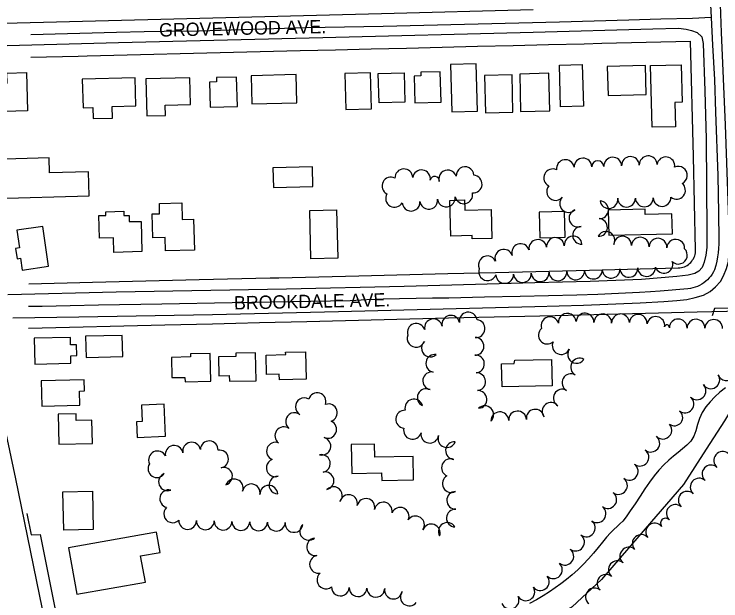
# Model space of a CAD drawing. Extents: x -25029 to 2274964, y -81170 to 687028.
# Drawn here: x -18399 to -17603, y -67227 to -66567 of the extents above; entities that cross this region are included whole.
import ezdxf

# ---------------------------------------------------------------- set-up
doc = ezdxf.new("R2010")
doc.units = 0
for name, color, linetype in [('81911BEA - RW_X_Fee_RW', 7, 'Continuous'), ('BLDG', 7, 'Continuous'), ('CULVERT', 7, 'Continuous'), ('GE_X_CL_2000', 7, 'Continuous'), ('ROAD', 7, 'Continuous'), ('ROAD-NAME', 7, 'Continuous'), ('TREES', 7, 'Continuous'), ('WATER', 7, 'Continuous')]:
    doc.layers.add(name, color=color, linetype=linetype)

msp = doc.modelspace()

# ---------------------------------------------------------------- linework, layer by layer
at = {"layer": '81911BEA - RW_X_Fee_RW'}
for p, q in [((-18379.53, -67152.95), (-18369.44, -67152.7)), ((-18369.44, -67152.7), (-18310.53, -67445.07))]:
    msp.add_line(p, q, dxfattribs=at)
for points in [[(-18380.26, -66615.06), (-18326.66, -66613.75), (-18316.66, -66613.51), (-18256.68, -66612.04), (-18196.7, -66610.58), (-18136.71, -66609.12), (-18076.73, -66607.66), (-18036.74, -66606.68), (-17996.75, -66605.71), (-17956.76, -66604.73), (-17916.77, -66603.75), (-17876.78, -66602.78), (-17836.79, -66601.8), (-17796.81, -66600.83), (-17756.82, -66599.85), (-17736.82, -66599.37), (-17686.84, -66598.15), (-17636.85, -66596.93)], [(-17631.12, -66831.87), (-17633.68, -66726.89), (-17636.85, -66596.93)], [(-17650.63, -66852.35), (-17648.89, -66852.23), (-17647.16, -66851.96), (-17645.47, -66851.54), (-17643.82, -66850.98), (-17642.22, -66850.27), (-17640.7, -66849.43), (-17639.25, -66848.45), (-17637.89, -66847.36), (-17636.63, -66846.15), (-17635.48, -66844.83), (-17634.46, -66843.42), (-17633.56, -66841.93), (-17632.79, -66840.36), (-17632.16, -66838.74), (-17631.68, -66837.06), (-17631.34, -66835.35), (-17631.15, -66833.61), (-17631.12, -66831.87)], [(-18382.46, -66870.19), (-18310.45, -66868.44), (-18250.46, -66866.98), (-18190.48, -66865.51), (-18110.62, -66863.57), (-18100.5, -66863.32), (-18070.51, -66862.59), (-18010.43, -66861.12), (-17910.4, -66858.68), (-17856.57, -66857.37), (-17750.6, -66854.79), (-17650.63, -66852.35)], [(-18382.89, -66920.22), (-18229.25, -66916.47), (-18175.27, -66915.16), (-18149.27, -66914.52), (-18122.28, -66913.86), (-18069.29, -66912.57), (-17909.34, -66908.67), (-17789.37, -66905.75), (-17629.41, -66901.85), (-17579.43, -66900.63)], [(-18384.68, -67128.73), (-18379.53, -67152.95)]]:
    msp.add_lwpolyline(points, dxfattribs=at)
at = {"layer": 'BLDG'}
for points in [[(-18431.62, -66622.02), (-18431.03, -66645), (-18406.79, -66644.37), (-18407.08, -66632.99), (-18384.8, -66632.41), (-18383.68, -66675.43), (-18463.65, -66677.51), (-18465.07, -66622.89)], [(-17907.14, -66623.09), (-17905.74, -66676.66), (-17876.82, -66675.91), (-17878.22, -66622.34)], [(-17758.79, -66623.38), (-17757.58, -66670.2), (-17783.34, -66670.87), (-17784.55, -66624.05)], [(-17729.77, -66658.26), (-17686.84, -66657.14), (-17687.7, -66624.23), (-17730.63, -66625.34)], [(-17647.28, -66623.56), (-17646.19, -66665.76), (-17654.51, -66665.97), (-17653.8, -66693.28), (-17679.98, -66693.96), (-17681.79, -66624.46)], [(-18131.07, -66667.72), (-18080.24, -66666.4), (-18081.06, -66634.54), (-18131.89, -66635.86)], [(-18026.23, -66633.52), (-18025.18, -66673.9), (-17996.19, -66673.14), (-17997.24, -66632.77)], [(-17959.49, -66632.68), (-17958.64, -66665.6), (-17987.81, -66666.35), (-17988.67, -66633.44)], [(-17940.75, -66631.91), (-17940.64, -66636.19), (-17948.32, -66636.39), (-17947.54, -66666.36), (-17917.93, -66665.59), (-17918.82, -66631.35)], [(-17869.12, -66635.64), (-17868.02, -66677.69), (-17836.87, -66676.88), (-17837.96, -66634.83)], [(-17829.34, -66633.98), (-17828.24, -66676.35), (-17795.5, -66675.5), (-17796.6, -66633.13)], [(-18321.25, -66671.89), (-18310.04, -66671.6), (-18309.72, -66684.12), (-18287.92, -66683.56), (-18288.26, -66670.57), (-18261.83, -66669.88), (-18262.65, -66638.36), (-18322.08, -66639.9)], [(-18249.31, -66681.18), (-18228.32, -66680.64), (-18228.62, -66669.05), (-18200.27, -66668.31), (-18201.05, -66638.22), (-18250.4, -66639.51)], [(-18171.03, -66637.98), (-18170.9, -66642.78), (-18178.72, -66642.99), (-18177.98, -66671.42), (-18147.37, -66670.62), (-18148.23, -66637.39)], [(-18421.04, -66774.04), (-18314.41, -66771.27), (-18315.12, -66744.11), (-18359.13, -66745.25), (-18359.57, -66728.52), (-18422.18, -66730.15)], [(-18106.78, -66761.73), (-18062.29, -66760.57), (-18062.86, -66738.64), (-18107.35, -66739.8)], [(-18234.94, -66791.37), (-18235.24, -66779.64), (-18210, -66778.99), (-18209.51, -66797.85), (-18196.7, -66797.52), (-18195.8, -66832.43), (-18228.26, -66833.27), (-18228.66, -66818.14), (-18242.8, -66818.51), (-18243.5, -66791.59)], [(-17891.51, -66775.8), (-17891.21, -66787.23), (-17861.46, -66786.46), (-17860.61, -66819.14), (-17882.87, -66819.72), (-17882.97, -66815.83), (-17907.02, -66816.46), (-17908.07, -66776.23)], [(-18035.61, -66786.95), (-18034.2, -66841.43), (-18064.51, -66842.21), (-18065.93, -66787.74)], [(-17729.05, -66815.64), (-17657.21, -66813.77), (-17657.79, -66791.58), (-17687.92, -66792.36), (-17688.08, -66786.32), (-17729.78, -66787.4)], [(-18286.39, -66834.84), (-18286.82, -66818.27), (-18302.77, -66818.68), (-18303.42, -66793.46), (-18295.58, -66793.26), (-18295.69, -66789.04), (-18275.47, -66788.51), (-18275.34, -66793.49), (-18269.45, -66793.34), (-18269.27, -66800.25), (-18255.75, -66799.9), (-18254.86, -66834.02)], [(-17778.09, -66817.75), (-17778.84, -66788.88), (-17807.41, -66789.62), (-17806.66, -66818.49)], [(-18395.75, -66809.81), (-18392.95, -66829.81), (-18397.27, -66830.41), (-18395.64, -66842.09), (-18391.68, -66841.53), (-18389.83, -66854.71), (-18360.12, -66850.55), (-18366.4, -66805.7)], [(-18277.09, -66928.46), (-18318.42, -66929.36), (-18317.9, -66953.08), (-18276.58, -66952.18)], [(-18375.68, -66960.58), (-18334.86, -66959.69), (-18335.04, -66951.21), (-18328.27, -66951.06), (-18328.53, -66938.94), (-18335.32, -66939.09), (-18335.5, -66930.71), (-18376.31, -66931.6)], [(-18200.33, -66949.26), (-18200.26, -66952.64), (-18221.62, -66953.1), (-18221.13, -66975.88), (-18206.39, -66975.56), (-18206.28, -66980.52), (-18177.26, -66979.89), (-18177.94, -66948.77)], [(-18149.14, -66948.52), (-18149.06, -66952.05), (-18168.81, -66952.48), (-18168.34, -66973.78), (-18156.47, -66973.52), (-18156.33, -66979.99), (-18126.18, -66979.33), (-18126.86, -66948.03)], [(-18115.11, -66950.43), (-18092.96, -66949.94), (-18093.02, -66947.36), (-18070.51, -66946.86), (-18069.83, -66977.81), (-18100.08, -66978.47), (-18100.22, -66972.18), (-18114.63, -66972.5)], [(-17849.66, -66960.41), (-17835.54, -66960.1), (-17834.82, -66956.32), (-17793.5, -66955.42), (-17792.85, -66985.13), (-17849.1, -66986.36)], [(-18367.72, -67008.01), (-18324.82, -67007.07), (-18325.17, -66991.05), (-18319.66, -66990.93), (-18319.94, -66978.28), (-18368.35, -66979.34)], [(-18255.45, -67006.99), (-18254.68, -67025.27), (-18261.03, -67025.53), (-18260.28, -67043.27), (-18228.19, -67041.93), (-18229.7, -67005.91)], [(-18311.31, -67023.76), (-18329.02, -67024.14), (-18329.18, -67016.51), (-18349.36, -67016.95), (-18348.62, -67050.84), (-18310.74, -67050.02)], [(-17992.89, -67050.79), (-18019.29, -67051.36), (-18018.58, -67083.73), (-17984.95, -67083), (-17984.76, -67091.77), (-17948.78, -67090.98), (-17949.36, -67064.59), (-17992.57, -67065.53)], [(-18310.72, -67103.85), (-18309.77, -67147.03), (-18342.98, -67147.76), (-18343.93, -67104.57)], [(-18328.27, -67219.91), (-18251.07, -67206.12), (-18256.35, -67176.58), (-18234.5, -67172.68), (-18238.56, -67149.96), (-18337.61, -67167.65)]]:
    msp.add_lwpolyline(points, close=True, dxfattribs=at)
at = {"layer": 'CULVERT'}
msp.add_lwpolyline([(-17588.71, -66903.41), (-17588.82, -66897.84), (-17609.91, -66898.05), (-17612.46, -66906.31)], dxfattribs=at)
at = {"layer": 'GE_X_CL_2000'}
for points in [[(-17629.8, -66240.58), (-17628.04, -66246.5), (-17626.31, -66253.12), (-17624.8, -66259.8), (-17623.53, -66266.52), (-17622.48, -66273.28), (-17621.65, -66280.08), (-17621.06, -66286.89), (-17618.28, -66332.76), (-17616.11, -66375.01), (-17615.01, -66414.08), (-17613.91, -66457.6), (-17612.97, -66487.54), (-17613.75, -66522.98), (-17614.71, -66548.46), (-17613.45, -66570.36)], [(-17613.45, -66570.36), (-17634.63, -66571.35), (-17670.3, -66572.26), (-17682.31, -66572.62), (-17694.33, -66573.02), (-17706.34, -66573.48), (-17745.33, -66574.51), (-17784.32, -66575.47), (-17982.99, -66580.33), (-18026.68, -66581.26), (-18070.38, -66582.06), (-18190.3, -66585.63), (-18229.71, -66586.14), (-18252.48, -66586.53), (-18283.57, -66587.22), (-18380.05, -66590.03)], [(-17613.45, -66570.36), (-17611.96, -66601.54), (-17609.99, -66640.19), (-17608.87, -66676.92), (-17605.9, -66748.09), (-17605.23, -66790.77), (-17604.92, -66820.49), (-17605.02, -66825.39), (-17605.31, -66830.29), (-17605.81, -66835.18), (-17606.5, -66840.04), (-17607.38, -66844.88), (-17608.46, -66849.68), (-17609.73, -66854.43), (-17610.97, -66856.89), (-17612.38, -66859.24), (-17613.97, -66861.49), (-17615.72, -66863.61), (-17617.63, -66865.6), (-17619.68, -66867.43), (-17621.87, -66869.11), (-17624.17, -66870.62), (-17626.58, -66871.96), (-17629.09, -66873.11), (-17631.68, -66874.07), (-17634.33, -66874.83), (-17637.02, -66875.39), (-17639.76, -66875.75), (-17670.97, -66878.59), (-17681.8, -66879.23)], [(-17681.8, -66879.23), (-17694.45, -66879.98), (-17717.93, -66881.16), (-17741.43, -66882.13), (-17764.92, -66882.9), (-17828.62, -66884.34), (-17868.82, -66885.31), (-17909, -66886.37), (-17927.54, -66886.48), (-17946.08, -66886.73), (-17964.62, -66887.14), (-17983.17, -66887.69), (-18001.7, -66888.38), (-18020.24, -66889.22), (-18064.59, -66889.98), (-18108.93, -66890.81), (-18153.27, -66891.72), (-18232.35, -66893.1), (-18303.94, -66894.38), (-18335.68, -66894.98), (-18367.43, -66895.61), (-18382.68, -66895.92)]]:
    msp.add_lwpolyline(points, dxfattribs=at)
at = {"layer": 'ROAD'}
for points in [[(-17812.21, -66895.82), (-17757.25, -66894.33), (-17693.73, -66891.72), (-17666.98, -66890.09), (-17652.11, -66889.03), (-17641.04, -66887.72), (-17631.79, -66885.66), (-17622.4, -66883.09), (-17614.9, -66878.83), (-17608.63, -66873.82), (-17603.24, -66867.63), (-17599.83, -66861.36), (-17596.32, -66852.82), (-17594.21, -66845.07), (-17593.23, -66831.16), (-17593.43, -66808.82), (-17597.4, -66691.23), (-17601.98, -66587.04), (-17603.72, -66534.37)], [(-17814.14, -66561.82), (-17985.19, -66566.36), (-18204.18, -66571.65), (-18424.96, -66577.4)], [(-18434.91, -66602.58), (-18281.25, -66598.33), (-18051.04, -66592.73), (-17814, -66586.89)], [(-17814, -66586.89), (-17679.15, -66583.11), (-17650.51, -66582.44), (-17641.73, -66583.53), (-17635.58, -66585.04), (-17629.38, -66587.35), (-17624.21, -66591.93), (-17622.73, -66599.49), (-17620.85, -66652.82), (-17619.13, -66707.33), (-17618.5, -66811.64), (-17618.56, -66829.21), (-17619.5, -66838), (-17621.39, -66845.97), (-17623.71, -66851.88), (-17627.4, -66855.88), (-17632.18, -66858.78), (-17639.67, -66860.55), (-17652.42, -66862.14), (-17691.92, -66865.29), (-17749.73, -66867.8), (-17812.36, -66869.23)], [(-17812.36, -66869.23), (-17959.63, -66873.08), (-18091.86, -66876.18), (-18283.81, -66879.74), (-18405.9, -66882.63)], [(-18400.29, -66908.54), (-18326.11, -66907.38), (-18175.59, -66904.96), (-18033.58, -66901.44), (-17812.21, -66895.82)], [(-17660.8, -67547.08), (-17673.77, -67548.67), (-17689.07, -67551.03), (-17713.98, -67555.62), (-17799.7, -67575.86), (-17894.6, -67598.39), (-17974.6, -67615.75), (-18190.81, -67666.63), (-18261.32, -67683.42), (-18267.08, -67683.14), (-18271.85, -67681.34), (-18276.22, -67677.94), (-18278.68, -67671.35), (-18285.49, -67641.73), (-18303.85, -67546.41), (-18346.36, -67337.43), (-18370.27, -67220.16), (-18396.95, -67089.91), (-18428.22, -66944.68)]]:
    msp.add_lwpolyline(points, dxfattribs=at)
at = {"layer": 'TREES'}
for centre, radius, start, end in [((-17777.88, -66740.47), 10, 8.46199, 188.46199), ((-17757.99, -66738.75), 10, 1.41719, 181.41719), ((-17724.51, -66737.77), 10, 2.32072, 182.32072), ((-17704.53, -66736.96), 10, 2.32072, 182.32072), ((-17684.54, -66736.15), 10, 2.32072, 182.32072), ((-17664.68, -66737.36), 10, 350.71242, 170.71242), ((-17890.89, -66748.47), 10, 3.39401, 183.39401), ((-17741.25, -66738.34), 6.75, 1.41719, 181.41719), ((-17650.58, -66748.03), 10, 295.03508, 115.03508), ((-17959.82, -66750.87), 10, 2.10869, 182.10869), ((-17939.95, -66752.02), 10, 351.25038, 171.25038), ((-17910.41, -66752.08), 10, 17.55983, 197.55983), ((-17792.19, -66750.91), 10, 63.73528, 243.73528), ((-17974.42, -66760.11), 10, 62.62185, 242.62185), ((-17925, -66754.32), 5.12, 351.25038, 171.25038), ((-17881.73, -66757.85), 10, 265.29671, 85.29671), ((-17788.95, -66766.3), 10, 140.06114, 320.06114), ((-17652.65, -66764.86), 10, 230.9758, 50.9758), ((-17970.33, -66773.95), 10, 150.26756, 330.26756), ((-17892.31, -66769.99), 10, 192.5708, 12.5708), ((-17951.67, -66778.3), 10, 183.53679, 3.53679), ((-17931.78, -66776.3), 10, 187.92198, 7.92198), ((-17911.97, -66773.54), 10, 187.92198, 7.92198), ((-17774.23, -66779.81), 10, 134.84021, 314.84021), ((-17739.32, -66786.77), 10, 266.56471, 86.56471), ((-17728.82, -66775.37), 10, 188.15911, 8.15911), ((-17708.93, -66773.8), 10, 180.86414, 0.86414), ((-17688.93, -66773.5), 10, 180.85266, 0.85266), ((-17668.94, -66772.99), 10, 182.05625, 2.05625), ((-17763.67, -66796.26), 10, 110.58794, 290.58794), ((-17740.49, -66806.73), 10, 266.77019, 86.77019), ((-17759.63, -66815.61), 10, 92.95734, 272.95734), ((-17789, -66828.22), 10, 5.00841, 185.00841), ((-17769.08, -66826.47), 10, 5.00841, 185.00841), ((-17732.22, -66821.41), 10, 331.99609, 151.99609), ((-17713.41, -66826.69), 10, 356.6851, 176.6851), ((-17693.44, -66827.84), 10, 356.6851, 176.6851), ((-17828.24, -66835.1), 10, 18.63115, 198.63115), ((-17808.86, -66830.5), 10, 8.10471, 188.10471), ((-17673.47, -66829), 10, 356.6851, 176.6851), ((-17653.51, -66830.16), 10, 356.6851, 176.6851), ((-17847.19, -66841.49), 10, 18.63115, 198.63115), ((-17650.46, -66837.94), 10, 226.0819, 46.0819), ((-17865.76, -66848.86), 10, 24.63908, 204.63908), ((-17666.9, -66848.27), 10, 198.22592, 18.22592), ((-17865.51, -66856.61), 10, 158.98243, 338.98243), ((-17826.21, -66858.73), 10, 182.80305, 2.80305), ((-17806.24, -66857.75), 10, 182.80305, 2.80305), ((-17786.26, -66856.78), 10, 182.80305, 2.80305), ((-17766.29, -66855.8), 10, 182.80305, 2.80305), ((-17746.31, -66854.82), 10, 182.80305, 2.80305), ((-17726.33, -66853.84), 10, 182.80305, 2.80305), ((-17706.36, -66852.86), 10, 182.80305, 2.80305), ((-17686.38, -66851.89), 10, 182.80305, 2.80305), ((-17846.19, -66859.71), 10, 182.80305, 2.80305), ((-17906.95, -66915.74), 10, 11.72635, 191.72635), ((-17887.28, -66912.2), 10, 8.70873, 188.70873), ((-17775.66, -66913.58), 10, 5.11966, 185.11966), ((-17755.72, -66913.25), 10, 356.75729, 176.75729), ((-17735.74, -66914.13), 10, 358.19679, 178.19679), ((-17715.75, -66914.21), 10, 1.34756, 181.34756), ((-17695.78, -66914.7), 10, 355.89203, 175.89203), ((-17926.53, -66919.81), 10, 11.72635, 191.72635), ((-17878.37, -66920.64), 10, 264.39724, 84.39724), ((-17795.17, -66917.45), 10, 17.30012, 197.30012), ((-17675.95, -66917.1), 10, 350.26037, 170.26037), ((-17650.68, -66919.87), 10, 359.14717, 179.14717), ((-17630.69, -66920.17), 10, 359.14717, 179.14717), ((-17610.69, -66920.47), 10, 359.14717, 179.14717), ((-17945.84, -66924.92), 10, 17.90861, 197.90861), ((-17798.19, -66928), 10, 130.74419, 310.74419), ((-17663.39, -66919.26), 2.74, 350.26037, 170.26037), ((-17946.04, -66931.62), 10, 158.71039, 338.71039), ((-17929.98, -66942.64), 10, 132.41609, 312.41609), ((-17879.6, -66940.59), 10, 268.5126, 88.5126), ((-17782.6, -66939.8), 10, 155.00242, 335.00242), ((-17765.28, -66949.66), 10, 145.70779, 325.70779), ((-17924.99, -66959.86), 10, 79.8948, 259.8948), ((-17879.15, -66960.56), 10, 274.0756, 94.0756), ((-17761.86, -66964.04), 10, 61.02111, 241.02111), ((-17928.49, -66979.55), 10, 79.8948, 259.8948), ((-17596.32, -66969.21), 10, 201.66467, 21.66467), ((-17877.73, -66980.51), 10, 274.0756, 94.0756), ((-17771.55, -66981.54), 10, 61.02111, 241.02111), ((-17614.01, -66978.35), 10, 212.97, 32.97), ((-17629.55, -66990.78), 10, 224.35066, 44.35066), ((-18057.5, -67003.03), 10, 342.55101, 162.55101), ((-17934.61, -66998.4), 10, 64.1432, 244.1432), ((-17876.31, -67000.46), 10, 274.0756, 94.0756), ((-17781.36, -66998.96), 10, 60.20562, 240.20562), ((-18071.94, -67008.75), 10, 60.70355, 240.70355), ((-17948.61, -67010.05), 10, 15.415, 195.415), ((-17643.06, -67005.49), 10, 230.50998, 50.50998), ((-18044.85, -67015.53), 10, 288.12074, 108.12074), ((-17868.64, -67017.61), 10, 314.0949, 134.0949), ((-17794.13, -67013.9), 10, 38.74292, 218.74292), ((-18083.03, -67025.32), 10, 51.72132, 231.72132), ((-17958.99, -67022.69), 10, 85.78261, 265.78261), ((-17851.69, -67024.41), 10, 2.1918, 182.1918), ((-17831.71, -67023.54), 10, 2.77843, 182.77843), ((-17811.82, -67021.61), 10, 8.34159, 188.34159), ((-17655.06, -67020.72), 9.4, 233.08904, 53.08904), ((-18045.64, -67034.24), 10, 247.062, 67.062), ((-18095.06, -67041.29), 10, 54.26694, 234.26694), ((-17950.1, -67035.37), 10, 164.26999, 344.26999), ((-17668.02, -67035.05), 10, 222.96208, 42.96208), ((-17930.59, -67039.59), 10, 171.32087, 351.32087), ((-17911.35, -67044.63), 10, 159.31456, 339.31456), ((-17681.57, -67049.69), 10, 231.47143, 51.47143), ((-18198.91, -67058.6), 10, 10.65252, 190.65252), ((-18179.09, -67057.21), 10, 357.37943, 177.37943), ((-18104.5, -67058.73), 10, 68.88587, 248.88587), ((-18052.15, -67053.11), 10, 254.85011, 74.85011), ((-17902.77, -67058.13), 10, 85.51032, 265.51032), ((-18218.56, -67062.3), 10, 10.65252, 190.65252), ((-18167.44, -67067.53), 10, 279.56031, 99.56031), ((-17693.84, -67065.48), 10, 232.8274, 52.8274), ((-18237.39, -67068.51), 10, 25.87243, 205.87243), ((-18052.74, -67072.55), 10, 281.69863, 101.69863), ((-17600.67, -67069.2), 10, 50.54616, 230.54616), ((-18238.04, -67078.39), 10, 146.5515, 326.5515), ((-18104.77, -67077.49), 10, 109.49043, 289.49043), ((-17907.39, -67077.34), 10, 67.43083, 247.43083), ((-17705.93, -67081.41), 10, 232.8274, 52.8274), ((-18163.02, -67087), 10, 286.03919, 106.03919), ((-17613.74, -67084.34), 10, 47.8361, 227.8361), ((-18226.06, -67093.21), 10, 111.35079, 291.35079), ((-18101.7, -67096.91), 10, 88.49176, 268.49176), ((-18048.59, -67092.11), 10, 282.26933, 102.26933), ((-17906.41, -67095.33), 10, 118.82435, 298.82435), ((-17718.01, -67097.35), 10, 232.8274, 52.8274), ((-17627.16, -67099.16), 10, 47.8361, 227.8361), ((-18150.91, -67100.16), 10, 339.18408, 159.18408), ((-18131.75, -67105.68), 10, 348.6981, 168.6981), ((-18111.95, -67107.27), 10, 2.08318, 182.08318), ((-18224.77, -67112.24), 10, 76.4127, 256.4127), ((-18039.15, -67108.71), 10, 316.96858, 136.96858), ((-17901.41, -67114.09), 10, 91.0095, 271.0095), ((-17730.09, -67113.29), 10, 232.8274, 52.8274), ((-17640.59, -67113.99), 10, 47.8361, 227.8361), ((-18022.08, -67117.71), 10, 347.43019, 167.43019), ((-18002.56, -67122.06), 10, 347.43019, 167.43019), ((-17982.98, -67126.12), 10, 349.17917, 169.17917), ((-17742.18, -67129.22), 10, 232.8274, 52.8274), ((-17654.01, -67128.81), 10, 47.8361, 227.8361), ((-18220.28, -67129.27), 10, 133.09473, 313.09473), ((-17964.02, -67132.05), 10, 336.05703, 156.05703), ((-17901.76, -67134.08), 10, 87.008, 267.008), ((-18203.45, -67136.76), 10, 178.88549, 358.88549), ((-18183.46, -67137.15), 10, 178.88549, 358.88549), ((-18163.46, -67137.54), 10, 178.88549, 358.88549), ((-17946.61, -67141.74), 10, 325.7503, 145.7503), ((-17754.26, -67145.16), 10, 232.8274, 52.8274), ((-17665.08, -67139.81), 5.64, 39.47587, 219.47587), ((-18143.46, -67137.93), 10, 178.88549, 358.88549), ((-18123.47, -67138.32), 10, 178.88549, 358.88549), ((-18103.47, -67138.71), 10, 178.88549, 358.88549), ((-18083.56, -67140.19), 10, 172.60133, 352.60133), ((-18067.04, -67148.99), 10, 131.32979, 311.32979), ((-17928.94, -67150.77), 10, 340.10895, 160.10895), ((-17910.91, -67149.12), 10, 30.36044, 210.36044), ((-17677.15, -67149.75), 10, 39.47587, 219.47587), ((-17766.35, -67161.1), 10, 232.8274, 52.8274), ((-17692.4, -67162.69), 10, 41.14754, 221.14754), ((-18059.17, -67166.42), 10, 97.27146, 277.27146), ((-17778.43, -67177.03), 10, 232.8274, 52.8274), ((-17706.38, -67176.92), 10, 49.86641, 229.86641), ((-18055.96, -67186.15), 10, 101.16714, 281.16714), ((-17791.37, -67192.24), 10, 226.415, 46.415), ((-17719.27, -67192.21), 10, 49.86641, 229.86641), ((-18047.69, -67203.7), 10, 129.30693, 309.30693), ((-17806.1, -67205.7), 10, 218.39812, 38.39812), ((-17732.16, -67207.5), 10, 49.86641, 229.86641), ((-18031.36, -67211.8), 10, 177.8835, 357.8835), ((-18011.38, -67212.51), 10, 178.05151, 358.05151), ((-17991.39, -67213.19), 10, 178.05151, 358.05151), ((-17971.53, -67215.18), 10, 170.51608, 350.51608), ((-17953.73, -67222.91), 10, 142.56954, 322.56954), ((-17822.43, -67217.19), 10, 211.89004, 31.89004), ((-17745.05, -67222.79), 10, 49.86641, 229.86641), ((-17840.12, -67226.39), 10, 203.06545, 23.06545)]:
    msp.add_arc(centre, radius, start, end, dxfattribs=at)
at = {"layer": 'WATER'}
for points in [[(-17541.82, -66980.56), (-17545.98, -66982.44), (-17551.32, -66984.88), (-17551.68, -66985.06), (-17572.33, -66994.58), (-17587.79, -67006.51), (-17598.4, -67024.62), (-17619.16, -67056.41), (-17644.79, -67096.16), (-17695.07, -67154.4), (-17737.04, -67203.42), (-17770.18, -67233.89), (-17837.33, -67272.76), (-17907.25, -67298.38)], [(-17597.57, -66987.25), (-17603.89, -66992.38), (-17609.53, -66997.63), (-17614.69, -67003.12), (-17619.48, -67008.95), (-17623.67, -67015.16), (-17626.92, -67021.78), (-17629.12, -67028.75), (-17630.93, -67035.65), (-17633.21, -67041.97), (-17636.62, -67047.35)], [(-17636.62, -67047.35), (-17640.95, -67051.96), (-17645.78, -67056.13), (-17650.77, -67060.18), (-17655.9, -67064.37), (-17661.23, -67068.99), (-17666.77, -67074.24), (-17672.38, -67080.13), (-17677.87, -67086.62), (-17683.12, -67093.67), (-17688.29, -67101.26), (-17693.63, -67109.39), (-17699.22, -67117.9), (-17704.67, -67125.99), (-17709.45, -67132.7), (-17713.22, -67137.39), (-17716.37, -67140.7), (-17719.52, -67143.6), (-17723.12, -67146.88), (-17727.17, -67150.83), (-17731.53, -67155.56), (-17736.11, -67161.13), (-17740.96, -67167.29), (-17746.17, -67173.71), (-17751.78, -67180.12), (-17757.72, -67186.36), (-17763.88, -67192.32), (-17770.15, -67197.92), (-17776.5, -67203.17), (-17782.88, -67208.11), (-17789.29, -67212.78), (-17795.9, -67217.26), (-17802.91, -67221.63), (-17810.44, -67225.97), (-17818.37, -67230.27)]]:
    msp.add_lwpolyline(points, dxfattribs=at)

# ---------------------------------------------------------------- texts
at = {"layer": 'ROAD-NAME'}
for s, p in [('GROVEWOOD AVE.', (-18235.45, -66591.87)), ('BROOKDALE AVE.', (-18151.08, -66899.21))]:
    msp.add_text(s, height=15, rotation=1.19807, dxfattribs=at).set_placement(p)

doc.saveas('drawing.dxf')
